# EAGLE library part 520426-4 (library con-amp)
AMP connector
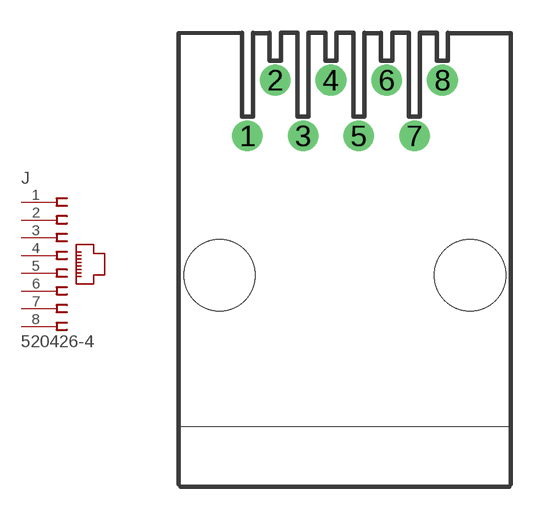
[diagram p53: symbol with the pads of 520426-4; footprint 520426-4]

Designator prefix J

## 520426-4 (MF: TYCO ELECTRONICS; MPN: 5520426-4; OC_FARNELL: 1557668; OC_NEWARK: 42K7232)  [520426-4]
1  1  pas
2  2  pas
3  3  pas
4  4  pas
5  5  pas
6  6  pas
7  7  pas
8  8  pas

## Footprint 520426-4 (pad centres in mm)
Modular Jack without Panel Stops
drill 0.889 round: 1 -4.445,6.35; 2 -3.175,8.89; 3 -1.905,6.35; 4 -0.635,8.89; 5 0.635,6.35; 6 1.905,8.89; 7 3.175,6.35; 8 4.445,8.89
hole 3.251 at -5.715,0
hole 3.251 at 5.715,0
